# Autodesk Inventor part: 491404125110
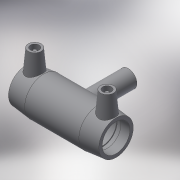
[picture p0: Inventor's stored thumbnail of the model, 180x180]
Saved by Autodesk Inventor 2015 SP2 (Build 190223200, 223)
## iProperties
Created: 2017-06
Part Number: 491404125110
Material: Generic
Description: PLASSON REDUCING TEE 125x110x125
Document SubType Name: Modeling
Designer: KIM
Mass: 57.3761 g
Surface Area: 241.06 cm^2
Volume: 57.3761 cm^3
Density: 1 g/cm^3
Appearance: Default
Author: KIM
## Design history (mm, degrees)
derived "491404.ipt"
feature "Solid1::491404.ipt"
tag "TaggingFeature1"
body "Solid1"
other parameters: "d0" = 382, "d1" = 125, "d2" = 165, "d3" = 86, "d4" = 76.4, "d5" = 148.5, "d6" = 118.75, "d7" = 125, "d8" = 168 deg, "d10" = 34.4, "d11" = 11.46667, "d13" = 382, "d14" = 17.6296, "d17" = 112.5, "d18" = 125, "d19" = 3.52592, "d20" = 168 deg, "d22" = 153.45, "d23" = 165, "d25" = 135 deg, "d26" = 267.4, "d29" = 88, "d30" = 15, "d31" = 152.8, "d34" = 5 deg, "d35" = 15, "d39" = 5 deg, "d41" = 4, "d42" = 14, "d43" = 0, "d45" = 4, "d46" = 6, "d47" = 0, "d48" = -173, "d51" = 0, "d52" = 88, "d54" = 0, "d55" = 148.5, "d56" = 165, "d57" = 133.7, "d58" = 135 deg, "d59" = 86, "d60" = 86, "d61" = 135 deg, "d62" = 173, "d72" = 173.81, "d73" = 86.905, "d74" = -173, "d75" = 115.5, "d77" = 0, "d78" = 88, "d80" = 0, "d82" = 90.5, "d83" = 0, "d84" = 3, "d85" = 0, "d86" = 28.66667, "d87" = 150.381, "d88" = 11.46667, "d89" = 3, "d90" = 0, "d_" = 125, "L_" = 382, "L_1" = 86, "D_" = 165, "A_" = 88, "d_2" = 12, "H_" = 173
